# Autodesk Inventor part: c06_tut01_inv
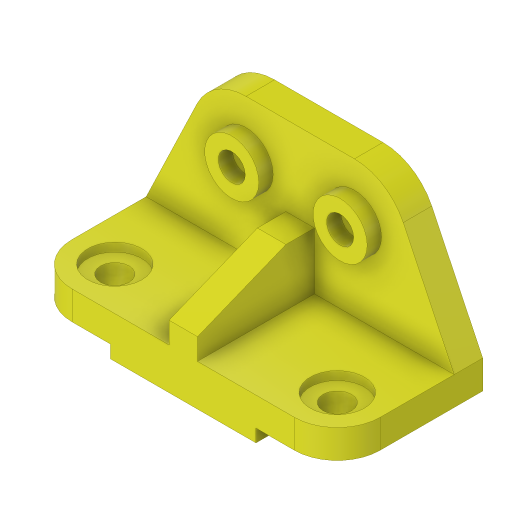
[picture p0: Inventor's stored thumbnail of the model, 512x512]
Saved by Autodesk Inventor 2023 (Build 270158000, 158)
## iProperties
Created: 2015-03
Part Number: c06_tut01_inv
Material: Generic
Document SubType Name: Modeling
Designer: Sandeep
Density: 1 g/cm^3
Appearance: Yellow
Author: Sandeep
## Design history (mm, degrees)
sketch "Sketch1"
  geometry: L1 (51, 0)-(51, 9); L2 (51, 9)-(108, 9); L3 (108, 9)-(108, 29); L4 (108, 29)-(-108, 29); L5 (-108, 29)-(-108, 9); L6 (-108, 9)-(-51, 9); L7 (-51, 9)-(-51, 0); L8 (-51, 0)-(51, 0); L9 (0, 96.725)-(0, -45.323); 1 further point
  constraints: 18 end point, 6 perpendicular, 3 point on line, 2 vertical, 1 midpoint, 2 other
  dimensions: "d1" = 20 distance of L2.end L3.end; "d2" = 57 distance between parallel lines of L5 L7; "d3" = 102 distance between parallel lines of L7 L1; "d66" = 9 distance between parallel lines of L2 L8
extrude "Extrusion1" new body sketch "Sketch1" distance "d4" = 102; taper "d5" = 0 deg
sketch "Sketch2"
  geometry: L1 (-108, -29)-(108, -29) reference; L2 (108, -29)-(72.256, -103.447); L3 (38, -125)-(-38, -125); L4 (-72.256, -103.447)-(-108, -29); L5 (0, -125)-(0, -29); L6 (51, 0)-(-51, 0) reference; A1 r 38 centre (38, -87) between (38, -125) and (72.256, -103.447); A2 r 38 centre (-38, -87) between (-72.256, -103.447) and (-38, -125); 2 further points
  constraints: 8 end point, 4 point on circle, 4 tangent, 3 midpoint, 2 centre point, 1 parallel, 1 point on line, 1 vertical, 2 other
  dimensions: "d6" = 96 distance between parallel lines of L1 L3; "d7" = 38 radius of A2; "d8" = 76 distance of L3.start L3.end
extrude "Extrusion2" join sketch "Sketch2" distance "d9" = 20; taper "d10" = 0 deg
sketch "Sketch3"
  geometry: L1 (0, 198.489)-(0, -42.784); L2 (38, 125)-(-38, 125) reference; C1 r 19 at (-38, 87); C2 r 9.5 at (-38, 87); C3 r 9.5 at (38, 87); C4 r 19 at (38, 87); 2 further points
  constraints: 4 centre point, 2 coincident, 2 end point, 2 equal radius, 1 midpoint, 1 point on line, 1 vertical, 2 other
  dimensions: "d11" = 38 diameter of C1; "d12" = 19 diameter of C2; "d13" = 76 distance of C3.centre C1.centre; "d14" = 38 distance from line of C1.centre L2
extrude "Extrusion3" join sketch "Sketch3" distance "d15" = 10; taper "d16" = 0 deg
fillet "Fillet1" dims "d17" = 30
hole "Hole3" diameter "d38" = 20; stored, may be unused: countersink angle "d42" = 90 deg, drill point angle "d44" = 118 deg; dims "d39" = 6, "d40" = 38, "d41" = 6, "d43" = 8, "d64" = 10, "d65" = 10
hole "Hole4" diameter "d47" = 20; stored, may be unused: countersink angle "d51" = 90 deg, drill point angle "d53" = 118 deg; dims "d45" = 10, "d46" = 10, "d48" = 6, "d49" = 38, "d50" = 6, "d52" = 8
workplane "Work Plane1"
sketch "Sketch4"
  geometry: L1 (-40, 0.112)-(-40, -20); L2 (-40, -20)-(-15, -82); L3 (20, -82)-(0, -82) reference; L4 (-15, -82)-(0, -82); L5 (0, -52)-(0, 0) reference; L6 (-96, 0)-(-74.447, 0) reference; 1 further point
  constraints: 6 end point, 1 collinear, 1 vertical
  dimensions: "d55" = 40 distance between parallel lines of L1 L5; "d56" = 20 distance from line of L6 L1.end; "d57" = 15 distance of L2.end L3.end
feature "Rib1" sketch "Sketch4" dims "d58" = 1, "d59" = 20, "d60" = 0, "d61" = 0, "d62" = 1, "d63" = 1
body "Solid1"
other parameters: "d54" = -108
